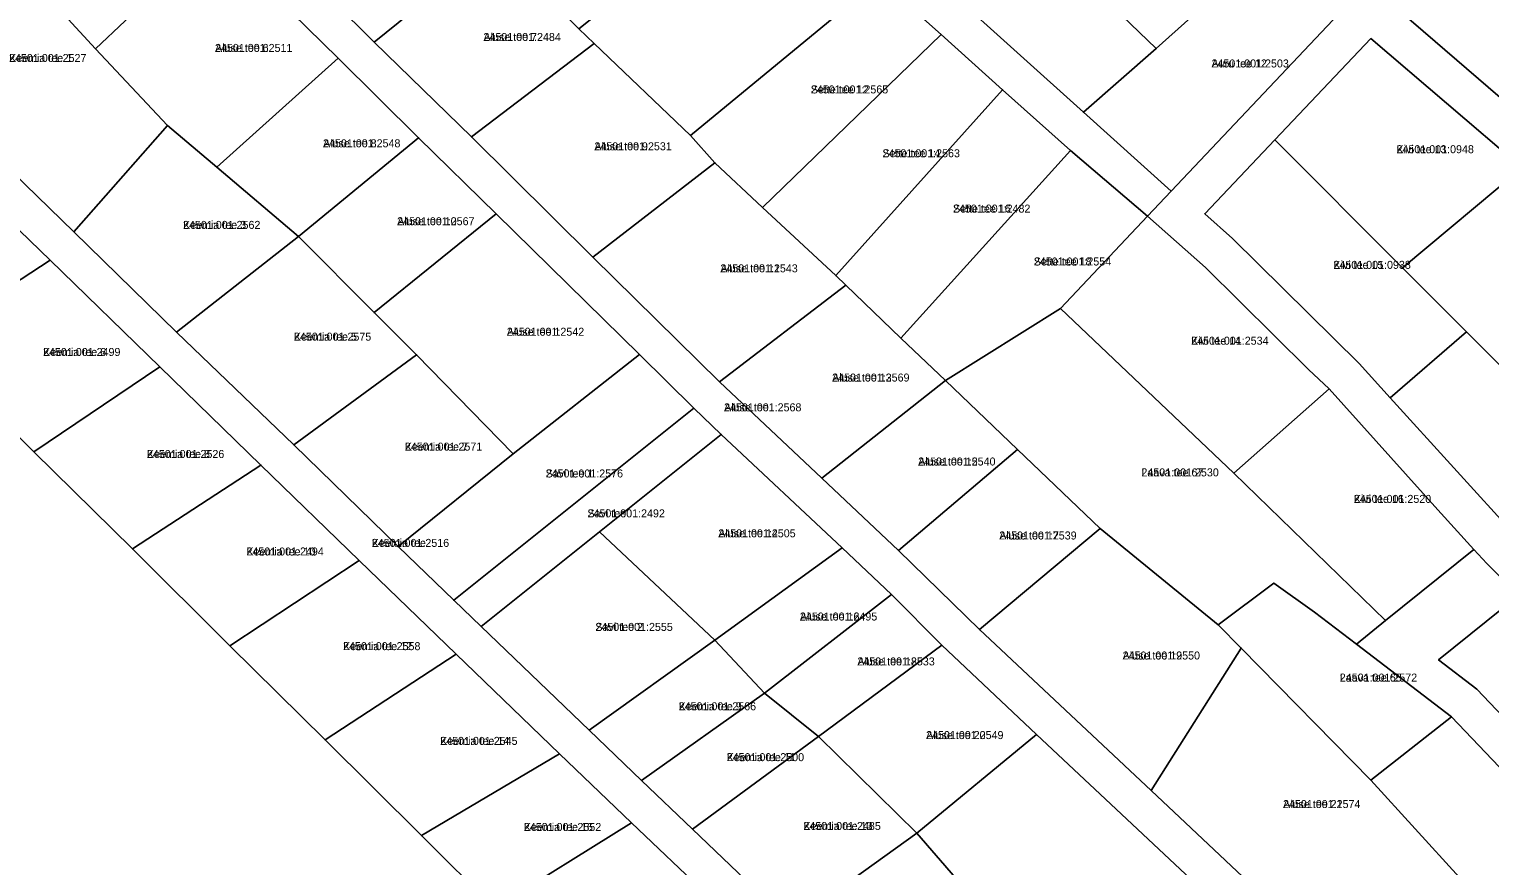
# Model space of a CAD drawing. Extents: x 551291 to 575799, y 6581704 to 6610137.
# Drawn here: x 559109.5 to 559383.3, y 6593475.6 to 6593632.5 of the extents above; entities that cross this region are included whole.
import ezdxf

# ---------------------------------------------------------------- set-up
doc = ezdxf.new("R2010")
doc.units = 0
for name, color, linetype in [('L_AADRESS', 7, 'Continuous'), ('PIIR', 7, 'Continuous'), ('TUNNUS', 7, 'Continuous')]:
    doc.layers.add(name, color=color, linetype=linetype)

msp = doc.modelspace()

# ---------------------------------------------------------------- linework, layer by layer
at = {"layer": 'PIIR'}
for points in [[(559179.59, 6593729.84), (559185.32, 6593733.99), (559214.48, 6593701.83), (559242.35, 6593675), (559269.17, 6593651.06), (559307.11, 6593616.9), (559323.52, 6593602.12), (559319.12, 6593597.39), (559304.66, 6593609.75), (559291.94, 6593621.11), (559280.42, 6593631.47), (559268.87, 6593641.79), (559249.64, 6593659.16), (559233.79, 6593673.7), (559221.66, 6593685.22), (559209.48, 6593697), (559193.77, 6593714.18), (559190.17, 6593718.15), (559188.12, 6593720.41)], [(559100.12, 6593652.42), (559124.12, 6593669.65), (559128.01, 6593665.84), (559144.16, 6593649.83), (559121.94, 6593628.77), (559103.5, 6593648.75)], [(559158.73, 6593645.4), (559180.74, 6593663.74), (559185.41, 6593659.26), (559196.66, 6593648.21), (559174.15, 6593630.04)], [(559269.17, 6593651.06), (559284.7, 6593663.42), (559289.48, 6593659), (559309.62, 6593639.6), (559320.74, 6593628.82), (559307.11, 6593616.9)], [(559395.61, 6593610.72), (559360.43, 6593641.06), (559378.93, 6593660.64), (559403, 6593640.02), (559416.54, 6593628.43)], [(559229.14, 6593645.87), (559249.64, 6593659.16), (559268.87, 6593641.79), (559233.47, 6593612.54), (559215.38, 6593629.77), (559212.54, 6593632.51)], [(559309.62, 6593639.6), (559333.26, 6593656.84), (559342.59, 6593648.47), (559320.74, 6593628.82)], [(559078.84, 6593632.41), (559076.02, 6593635.12), (559100.12, 6593652.42), (559103.5, 6593648.75), (559121.94, 6593628.77), (559135.44, 6593614.39), (559117.9, 6593594.47)], [(559121.94, 6593628.77), (559144.16, 6593649.83), (559167.42, 6593627.02), (559144.68, 6593606.58), (559135.44, 6593614.39)], [(559320.74, 6593628.82), (559342.59, 6593648.47), (559356.05, 6593636.44), (559323.52, 6593602.12), (559307.11, 6593616.9)], [(559174.15, 6593630.04), (559196.66, 6593648.21), (559200.24, 6593644.74), (559212.54, 6593632.51), (559215.38, 6593629.77), (559192.4, 6593612.28)], [(559233.47, 6593612.54), (559268.87, 6593641.79), (559280.42, 6593631.47), (559246.97, 6593599.05), (559238.03, 6593607.41)], [(559192.4, 6593612.28), (559215.38, 6593629.77), (559233.47, 6593612.54), (559238.03, 6593607.41), (559215.14, 6593589.75)], [(559246.97, 6593599.05), (559280.42, 6593631.47), (559291.94, 6593621.11), (559260.67, 6593586.28)], [(559366.93, 6593587.72), (559342.95, 6593611.69), (559360.96, 6593630.7), (559389.32, 6593606.49)], [(559144.68, 6593606.58), (559167.42, 6593627.02), (559182.49, 6593612.1), (559159.96, 6593593.61)], [(559260.67, 6593586.28), (559291.94, 6593621.11), (559304.66, 6593609.75), (559272.89, 6593574.54), (559262.56, 6593584.49)], [(559117.9, 6593594.47), (559135.44, 6593614.39), (559144.68, 6593606.58), (559159.96, 6593593.61), (559137.14, 6593575.65)], [(559159.96, 6593593.61), (559182.49, 6593612.1), (559197.06, 6593597.84), (559174.16, 6593579.32)], [(559335.03, 6593593.22), (559329.83, 6593597.85), (559342.95, 6593611.69), (559366.93, 6593587.72), (559378.92, 6593575.72), (559364.59, 6593563.37), (559358.78, 6593569.77)], [(559067.89, 6593595.43), (559092.11, 6593609.74), (559113.42, 6593589.15), (559089.79, 6593573.7)], [(559215.14, 6593589.75), (559238.03, 6593607.41), (559246.97, 6593599.05), (559260.67, 6593586.28), (559262.56, 6593584.49), (559238.92, 6593566.34)], [(559272.89, 6593574.54), (559304.66, 6593609.75), (559319.12, 6593597.39), (559302.83, 6593580.1), (559281.22, 6593566.57)], [(559378.92, 6593575.72), (559366.93, 6593587.72), (559389.32, 6593606.49), (559419.11, 6593580.47), (559394.61, 6593560.03)], [(559174.16, 6593579.32), (559197.06, 6593597.84), (559223.91, 6593571.45), (559200.24, 6593552.84), (559182.12, 6593571.44)], [(559302.83, 6593580.1), (559319.12, 6593597.39), (559329.96, 6593587.8), (559349.3, 6593568.68), (559353.15, 6593565.06), (559335.29, 6593549.23)], [(559137.14, 6593575.65), (559159.96, 6593593.61), (559174.16, 6593579.32), (559182.12, 6593571.44), (559159.08, 6593554.53)], [(559089.79, 6593573.7), (559113.42, 6593589.15), (559134.01, 6593569.13), (559110.4, 6593553.23)], [(559238.92, 6593566.34), (559262.56, 6593584.49), (559272.89, 6593574.54), (559281.22, 6593566.57), (559258.09, 6593548.31)], [(559281.22, 6593566.57), (559302.83, 6593580.1), (559335.29, 6593549.23), (559363.74, 6593521.61), (559358.28, 6593517.14), (559350.43, 6593523.17), (559342.77, 6593528.61), (559332.34, 6593520.76), (559310.25, 6593538.83), (559294.73, 6593553.68)], [(559388.48, 6593537.08), (559364.59, 6593563.37), (559378.92, 6593575.72), (559394.61, 6593560.03), (559414.67, 6593540.83), (559417.49, 6593538.13), (559401.12, 6593524.59)], [(559110.4, 6593553.23), (559134.01, 6593569.13), (559152.95, 6593550.74), (559128.84, 6593535.02)], [(559159.08, 6593554.53), (559182.12, 6593571.44), (559200.24, 6593552.84), (559178.64, 6593535.46)], [(559200.24, 6593552.84), (559223.91, 6593571.45), (559234.08, 6593561.39), (559189.08, 6593525.39), (559178.64, 6593535.46)], [(559258.09, 6593548.31), (559281.22, 6593566.57), (559294.73, 6593553.68), (559272.44, 6593534.75)], [(559335.29, 6593549.23), (559353.15, 6593565.06), (559373.54, 6593542.33), (559380.27, 6593534.92), (559363.74, 6593521.61)], [(559194.22, 6593520.49), (559189.08, 6593525.39), (559234.08, 6593561.39), (559239.21, 6593556.48), (559216.42, 6593538.25)], [(559216.42, 6593538.25), (559239.21, 6593556.48), (559261.89, 6593535.22), (559237.99, 6593517.91)], [(559272.44, 6593534.75), (559294.73, 6593553.68), (559310.25, 6593538.83), (559287.6, 6593519.89)], [(559128.84, 6593535.02), (559152.95, 6593550.74), (559171.33, 6593532.86), (559147.13, 6593516.85)], [(559287.6, 6593519.89), (559310.25, 6593538.83), (559332.34, 6593520.76), (559336.69, 6593516.43), (559319.77, 6593489.76)], [(559194.22, 6593520.49), (559216.42, 6593538.25), (559237.99, 6593517.91), (559214.49, 6593501.04)], [(559237.99, 6593517.91), (559261.89, 6593535.22), (559271.11, 6593526.49), (559247.35, 6593507.98)], [(559363.74, 6593521.61), (559380.27, 6593534.92), (559382.69, 6593532.27), (559388.67, 6593526.29), (559373.66, 6593514.2), (559380.83, 6593508.71), (559407.81, 6593480.38), (559435.5, 6593451.37), (559438.64, 6593448.01), (559429.05, 6593446.56), (559428.92, 6593448.05), (559407.99, 6593470.04), (559376.11, 6593503.53), (559358.28, 6593517.14)], [(559147.13, 6593516.85), (559171.33, 6593532.86), (559189.52, 6593515.26), (559164.96, 6593499.22)], [(559332.34, 6593520.76), (559342.77, 6593528.61), (559350.43, 6593523.17), (559358.28, 6593517.14), (559376.11, 6593503.53), (559360.94, 6593491.68), (559336.69, 6593516.43)], [(559247.35, 6593507.98), (559271.11, 6593526.49), (559280.55, 6593516.97), (559257.47, 6593499.88)], [(559373.66, 6593514.2), (559388.67, 6593526.29), (559401.49, 6593513.72), (559398.77, 6593511.46), (559423.97, 6593493.54), (559407.81, 6593480.38), (559380.83, 6593508.71)], [(559214.49, 6593501.04), (559237.99, 6593517.91), (559247.35, 6593507.98), (559224.24, 6593491.62)], [(559257.47, 6593499.88), (559280.55, 6593516.97), (559298.28, 6593500.23), (559275.85, 6593481.76)], [(559164.96, 6593499.22), (559189.52, 6593515.26), (559208.91, 6593496.6), (559183.01, 6593481.29)], [(559319.77, 6593489.76), (559336.69, 6593516.43), (559360.94, 6593491.68), (559377.61, 6593473.41), (559355.16, 6593456.45)], [(559224.24, 6593491.62), (559247.35, 6593507.98), (559257.47, 6593499.88), (559233.84, 6593482.47)], [(559360.94, 6593491.68), (559376.11, 6593503.53), (559407.99, 6593470.04), (559391.57, 6593458.83), (559377.61, 6593473.41)], [(559233.84, 6593482.47), (559257.47, 6593499.88), (559275.85, 6593481.76), (559252.33, 6593464.79)], [(559275.85, 6593481.76), (559298.28, 6593500.23), (559337.16, 6593463.8), (559314.74, 6593444.9), (559303.89, 6593457.83), (559299.59, 6593454.27)], [(559183.01, 6593481.29), (559208.91, 6593496.6), (559222.42, 6593483.65), (559196.73, 6593467.68)], [(559196.73, 6593467.68), (559222.42, 6593483.65), (559236.46, 6593470.27), (559210.96, 6593453.7)], [(559252.33, 6593464.79), (559275.85, 6593481.76), (559299.59, 6593454.27), (559280.06, 6593438.12)]]:
    msp.add_lwpolyline(points, close=True, dxfattribs=at)
for points in [[(559337.16, 6593463.8), (559298.28, 6593500.23), (559280.55, 6593516.97), (559271.11, 6593526.49), (559261.89, 6593535.22), (559239.21, 6593556.48), (559234.08, 6593561.39), (559223.91, 6593571.45), (559197.06, 6593597.84), (559182.49, 6593612.1), (559167.42, 6593627.02), (559144.16, 6593649.83)], [(559158.73, 6593645.4), (559174.15, 6593630.04), (559192.4, 6593612.28), (559215.14, 6593589.75), (559238.92, 6593566.34), (559258.09, 6593548.31), (559272.44, 6593534.75), (559287.6, 6593519.89), (559319.77, 6593489.76), (559355.16, 6593456.45)], [(559388.67, 6593526.29), (559382.69, 6593532.27), (559380.27, 6593534.92), (559373.54, 6593542.33), (559353.15, 6593565.06), (559349.3, 6593568.68), (559329.96, 6593587.8), (559319.12, 6593597.39), (559323.52, 6593602.12), (559356.05, 6593636.44), (559360.43, 6593641.06), (559395.61, 6593610.72)], [(559078.84, 6593632.41), (559117.9, 6593594.47), (559137.14, 6593575.65), (559159.08, 6593554.53), (559178.64, 6593535.46), (559189.08, 6593525.39), (559194.22, 6593520.49), (559214.49, 6593501.04), (559224.24, 6593491.62), (559233.84, 6593482.47), (559252.33, 6593464.79)], [(559389.32, 6593606.49), (559360.96, 6593630.7), (559342.95, 6593611.69), (559329.83, 6593597.85), (559335.03, 6593593.22), (559358.78, 6593569.77), (559364.59, 6593563.37), (559388.48, 6593537.08)], [(559236.46, 6593470.27), (559222.42, 6593483.65), (559208.91, 6593496.6), (559189.52, 6593515.26), (559171.33, 6593532.86), (559152.95, 6593550.74), (559134.01, 6593569.13), (559113.42, 6593589.15), (559092.11, 6593609.74)], [(559089.79, 6593573.7), (559110.4, 6593553.23), (559128.84, 6593535.02), (559147.13, 6593516.85), (559164.96, 6593499.22), (559183.01, 6593481.29), (559196.73, 6593467.68), (559210.96, 6593453.7), (559228.35, 6593436.39), (559237.89, 6593426.94), (559249.59, 6593415.34), (559251.18, 6593413.78), (559255.43, 6593409.56), (559219.77, 6593403.64), (558957.47, 6593360.37)]]:
    msp.add_lwpolyline(points, dxfattribs=at)

# ---------------------------------------------------------------- texts
at = {"layer": 'L_AADRESS'}
for s, p in [('Aluse tee 6', (559144.34, 6593628.2)), ('Aluse tee 7', (559194.65, 6593630.25)), ('Keemia tee 1', (559105.73, 6593626.31)), ('Auru tee 12', (559331.1, 6593625.29)), ('Sette tee 12', (559256.01, 6593620.42)), ('Aluse tee 8', (559164.58, 6593610.32)), ('Aluse tee 9', (559215.44, 6593609.76)), ('Kivi tee 13', (559365.78, 6593609.21)), ('Sette tee 14', (559269.45, 6593608.45)), ('Sette tee 16', (559282.66, 6593598.08)), ('Keemia tee 3', (559138.34, 6593595.02)), ('Aluse tee 10', (559178.47, 6593595.71)), ('Aluse tee 11', (559239.05, 6593586.88)), ('Sette tee 18', (559297.8, 6593588.16)), ('Kivi tee 15', (559353.96, 6593587.53)), ('Keemia tee 5', (559159.12, 6593574.07)), ('Aluse tee 12', (559199.03, 6593574.99)), ('Kivi tee 14', (559327.29, 6593573.31)), ('Keemia tee 6', (559112.1, 6593571.19)), ('Aluse tee 13', (559260, 6593566.4)), ('Aluse tee', (559239.74, 6593560.82)), ('Keemia tee 8', (559131.57, 6593552.07)), ('Keemia tee 7', (559179.92, 6593553.45)), ('Savi tee 1', (559206.31, 6593548.42)), ('Aluse tee 15', (559276.12, 6593550.66)), ('Laava tee 67', (559317.97, 6593548.62)), ('Kivi tee 16', (559357.78, 6593543.65)), ('Savi tee', (559214.15, 6593540.94)), ('Keemia tee', (559173.72, 6593535.4)), ('Aluse tee 14', (559238.66, 6593537.2)), ('Aluse tee 17', (559291.32, 6593536.79)), ('Keemia tee 10', (559150.22, 6593533.79)), ('Aluse tee 16', (559253.96, 6593521.6)), ('Savi tee 2', (559215.63, 6593519.65)), ('Keemia tee 12', (559168.33, 6593516.04)), ('Aluse tee 18', (559264.73, 6593513.18)), ('Aluse tee 19', (559314.45, 6593514.29)), ('Laava tee 65', (559355.15, 6593510.15)), ('Keemia tee 9', (559231.24, 6593504.77)), ('Aluse tee 20', (559277.61, 6593499.37)), ('Keemia tee 14', (559186.54, 6593498.28)), ('Keemia tee 11', (559240.24, 6593495.23)), ('Aluse tee 21', (559344.51, 6593486.44)), ('Keemia tee 16', (559202.22, 6593482.14)), ('Keemia tee 13', (559254.62, 6593482.33))]:
    msp.add_text(s, height=1.5, dxfattribs=at).set_placement(p)
at = {"layer": 'TUNNUS'}
for s, p in [('24501:001:2511', (559144.34, 6593628.2)), ('24501:001:2484', (559194.65, 6593630.25)), ('24501:001:2527', (559105.73, 6593626.31)), ('24501:001:2503', (559331.1, 6593625.29)), ('24501:001:2565', (559256.01, 6593620.42)), ('24501:001:2548', (559164.58, 6593610.32)), ('24501:001:2531', (559215.44, 6593609.76)), ('24501:001:0948', (559365.78, 6593609.21)), ('24501:001:2563', (559269.45, 6593608.45)), ('24501:001:2482', (559282.66, 6593598.08)), ('24501:001:2562', (559138.34, 6593595.02)), ('24501:001:2567', (559178.47, 6593595.71)), ('24501:001:2543', (559239.05, 6593586.88)), ('24501:001:2554', (559297.8, 6593588.16)), ('24501:001:0938', (559353.96, 6593587.53)), ('24501:001:2575', (559159.12, 6593574.07)), ('24501:001:2542', (559199.03, 6593574.99)), ('24501:001:2534', (559327.29, 6593573.31)), ('24501:001:2499', (559112.1, 6593571.19)), ('24501:001:2569', (559260, 6593566.4)), ('24501:001:2568', (559239.74, 6593560.82)), ('24501:001:2526', (559131.57, 6593552.07)), ('24501:001:2571', (559179.92, 6593553.45)), ('24501:001:2576', (559206.31, 6593548.42)), ('24501:001:2540', (559276.12, 6593550.66)), ('24501:001:2530', (559317.97, 6593548.62)), ('24501:001:2520', (559357.78, 6593543.65)), ('24501:001:2492', (559214.15, 6593540.94)), ('24501:001:2516', (559173.72, 6593535.4)), ('24501:001:2505', (559238.66, 6593537.2)), ('24501:001:2539', (559291.32, 6593536.79)), ('24501:001:2494', (559150.22, 6593533.79)), ('24501:001:2495', (559253.96, 6593521.6)), ('24501:001:2555', (559215.63, 6593519.65)), ('24501:001:2558', (559168.33, 6593516.04)), ('24501:001:2533', (559264.73, 6593513.18)), ('24501:001:2550', (559314.45, 6593514.29)), ('24501:001:2572', (559355.15, 6593510.15)), ('24501:001:2566', (559231.24, 6593504.77)), ('24501:001:2549', (559277.61, 6593499.37)), ('24501:001:2545', (559186.54, 6593498.28)), ('24501:001:2500', (559240.24, 6593495.23)), ('24501:001:2574', (559344.51, 6593486.44)), ('24501:001:2552', (559202.22, 6593482.14)), ('24501:001:2485', (559254.62, 6593482.33))]:
    msp.add_text(s, height=1.5, dxfattribs=at).set_placement(p)

doc.saveas('drawing.dxf')
